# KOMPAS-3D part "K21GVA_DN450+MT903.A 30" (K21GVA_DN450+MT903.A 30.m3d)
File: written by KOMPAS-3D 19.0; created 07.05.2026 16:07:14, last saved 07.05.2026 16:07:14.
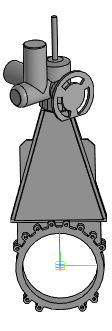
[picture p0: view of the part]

Document properties: Автор: Энергия; Полное имя файла: ..\K21GVA_DN50-DN1000+MT903.A\K21GVA_DN450+MT903.A 30.a3d

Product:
- Part/product: K21GVA_DN450+MT903.A 30
    Масса: 257.691

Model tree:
1. Операция без истории:1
